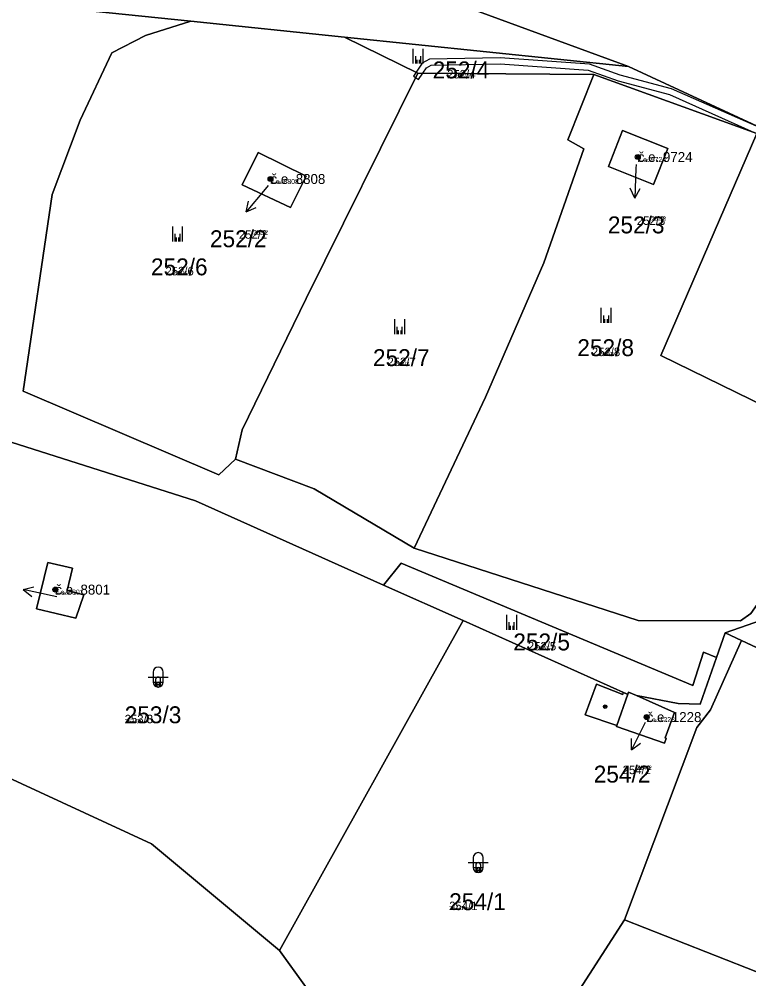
# Model space of a CAD drawing. Extents: x -759873 to -758487, y -975024 to -973516.
# Drawn here: x -758938.2 to -758864.9, y -974680.9 to -974584.4 of the extents above; entities that cross this region are included whole.
import ezdxf

# ---------------------------------------------------------------- set-up
doc = ezdxf.new("R2010")
doc.units = 0
for name, color, linetype in [('KAT_02_hranice parcel', 7, 'Continuous'), ('KAT_03_1000_st čísla parcelní', 7, 'Continuous'), ('KAT_03_1000_čísla parcelní', 7, 'Continuous'), ('KAT_03_1000_čísla popisná', 7, 'Continuous'), ('KAT_03_250_st čísla parcelní', 7, 'Continuous'), ('KAT_03_250_čísla parcelní', 7, 'Continuous'), ('KAT_03_250_čísla popisná', 7, 'Continuous'), ('KAT_03_500_st čísla parcelní', 7, 'Continuous'), ('KAT_03_500_čísla parcelní', 7, 'Continuous'), ('KAT_03_500_čísla popisná', 7, 'Continuous'), ('KAT_04_vnitřní kresba', 7, 'Continuous'), ('KAT_05_1000_značky kultur', 7, 'Continuous'), ('KAT_05_250_značky kultur', 7, 'Continuous'), ('KAT_05_500_značky kultur', 7, 'Continuous'), ('KAT_07_1000_značky budov', 7, 'Continuous'), ('KAT_07_250_značky budov', 7, 'Continuous'), ('KAT_07_500_značky budov', 7, 'Continuous'), ('KAT_10_věcná břemena', 7, 'Continuous'), ('KAT_12_pomocná šipka', 7, 'Continuous'), ('KAT_14_plocha_budovy', 7, 'Continuous'), ('KAT_14_plocha_pozemek', 7, 'Continuous')]:
    doc.layers.add(name, color=color, linetype=linetype)

msp = doc.modelspace()

# ---------------------------------------------------------------- linework, layer by layer
at = {"layer": 'KAT_02_hranice parcel'}
for p, q in [((-758920.93, -974584.62), (-758905.47, -974586.23)), ((-758905.47, -974586.23), (-758876.96, -974589.19)), ((-758905.47, -974586.23), (-758898.12, -974589.84)), ((-758898.12, -974589.84), (-758880.42, -974589.99)), ((-758880.42, -974589.99), (-758864.06, -974595.92)), ((-758893.55, -974644.86), (-758901.56, -974641.28)), ((-758912, -974678.02), (-758893.55, -974644.86)), ((-758877.14, -974652.2), (-758893.55, -974644.86)), ((-758868.1, -974648.55), (-758867.23, -974646.1)), ((-758865.59, -974646.87), (-758867.23, -974646.1)), ((-758830.87, -974663.12), (-758865.59, -974646.87)), ((-758892.74, -974704.7), (-758912, -974678.02))]:
    msp.add_line(p, q, dxfattribs=at)
for points in [[(-758909.19, -974563.8), (-758909.74, -974577.13), (-758876.96, -974589.19)], [(-758955.3, -974621.73), (-758944.2, -974593.65), (-758945.57, -974582.06), (-758920.93, -974584.62)], [(-758916.42, -974628.64), (-758918.11, -974630.21), (-758937.75, -974621.79), (-758934.83, -974602.03), (-758932.04, -974594.56), (-758928.85, -974587.8), (-758925.48, -974586.06), (-758920.93, -974584.62)], [(-758916.42, -974628.64), (-758915.75, -974625.68), (-758909.34, -974612.49), (-758898.12, -974589.84)], [(-758898.47, -974637.56), (-758891.31, -974622.41), (-758885.45, -974608.9), (-758881.45, -974597.46), (-758883.04, -974596.56), (-758880.42, -974589.99)], [(-758876.96, -974589.19), (-758848.43, -974602.4), (-758848.79, -974603.63)], [(-758873, -974597.42), (-758877.55, -974595.6), (-758878.95, -974599.23), (-758874.43, -974601.04), (-758873, -974597.42)], [(-758855.85, -974627.6), (-758861.57, -974624.14), (-758873.69, -974618.23), (-758864.06, -974595.92)], [(-758909.34, -974600.2), (-758914.17, -974597.83), (-758915.76, -974601.08), (-758910.91, -974603.34), (-758909.34, -974600.2)], [(-758955.3, -974621.73), (-758920.45, -974632.82), (-758901.56, -974641.28)], [(-758898.47, -974637.56), (-758908.53, -974631.63), (-758916.42, -974628.64)], [(-758857.61, -974633.6), (-758860.88, -974638), (-758862.68, -974641.33), (-758864.67, -974644.15), (-758865.71, -974644.88), (-758875.98, -974644.85), (-758898.47, -974637.56)], [(-758867.23, -974646.1), (-758860.6, -974643.76), (-758857.61, -974633.6)], [(-758932.8, -974639.6), (-758935.28, -974639.01), (-758936.41, -974643.67), (-758932.46, -974644.62), (-758931.67, -974642.25), (-758933.33, -974641.84), (-758932.8, -974639.6)], [(-758901.56, -974641.28), (-758899.78, -974639.1), (-758870.5, -974651.39), (-758869.41, -974648.04), (-758868.1, -974648.55)], [(-758877.35, -974674.93), (-758870.1, -974655.59), (-758868.73, -974653.83), (-758865.59, -974646.87)], [(-758868.1, -974648.55), (-758869.77, -974653.24), (-758871.96, -974653.19), (-758876.14, -974652.39)], [(-758876.14, -974652.39), (-758872.34, -974654.1), (-758873.26, -974656.65), (-758873.16, -974656.69), (-758873.33, -974657.16), (-758878.17, -974655.5), (-758878.14, -974655.39), (-758881.32, -974654.34), (-758880.17, -974651.24), (-758877.52, -974652.27), (-758877.48, -974652.09), (-758877.14, -974652.2)], [(-758876.14, -974652.39), (-758876.95, -974652.03), (-758877.01, -974652.25), (-758877.14, -974652.2)], [(-758912, -974678.02), (-758924.86, -974667.29), (-758949.14, -974656.07)], [(-758830.87, -974663.12), (-758834.94, -974670.75), (-758841.44, -974684.62), (-758853.59, -974681.81), (-758863.06, -974680.54), (-758877.35, -974674.93)], [(-758892.74, -974704.7), (-758892.08, -974697.79), (-758877.35, -974674.93)]]:
    msp.add_lwpolyline(points, dxfattribs=at)
at = {"layer": 'KAT_03_1000_čísla popisná'}
for centre in [(-758876.02, -974598.27), (-758912.91, -974600.48), (-758934.53, -974641.74), (-758875.13, -974654.55)]:
    msp.add_circle(centre, 0.25, dxfattribs=at)
at = {"layer": 'KAT_03_250_čísla popisná'}
for centre in [(-758876.02, -974598.27), (-758912.91, -974600.48), (-758934.53, -974641.74), (-758875.13, -974654.55)]:
    msp.add_circle(centre, 0.0625, dxfattribs=at)
at = {"layer": 'KAT_03_500_čísla popisná'}
for centre in [(-758876.02, -974598.27), (-758912.91, -974600.48), (-758934.53, -974641.74), (-758875.13, -974654.55)]:
    msp.add_circle(centre, 0.125, dxfattribs=at)
at = {"layer": 'KAT_04_vnitřní kresba'}
msp.add_line((-758878.14, -974655.39), (-758877.01, -974652.25), dxfattribs=at)
at = {"layer": 'KAT_05_1000_značky kultur'}
for p, q in [((-758898.581, -974588.89), (-758898.581, -974587.39)), ((-758897.58, -974588.89), (-758897.58, -974587.39)), ((-758922.741, -974606.75), (-758922.741, -974605.25)), ((-758921.74, -974606.75), (-758921.74, -974605.25)), ((-758879.701, -974614.94), (-758879.701, -974613.44)), ((-758878.7, -974614.94), (-758878.7, -974613.44)), ((-758900.431, -974616.08), (-758900.431, -974614.58)), ((-758899.43, -974616.08), (-758899.43, -974614.58)), ((-758889.181, -974645.77), (-758889.181, -974644.27)), ((-758888.18, -974645.77), (-758888.18, -974644.27)), ((-758925.201, -974650.531), (-758923.199, -974650.531)), ((-758924.701, -974650.031), (-758924.701, -974651.032)), ((-758923.699, -974651.032), (-758923.699, -974650.031)), ((-758892.551, -974668.671), (-758892.551, -974669.672)), ((-758891.549, -974669.672), (-758891.549, -974668.671)), ((-758893.051, -974669.171), (-758891.049, -974669.171))]:
    msp.add_line(p, q, dxfattribs=at)
for centre, start, end in [((-758924.2, -974650.031), 0, 180), ((-758924.2, -974651.031), 180, 359.98789), ((-758892.05, -974668.671), 0, 180), ((-758892.05, -974669.671), 180, 359.98789)]:
    msp.add_arc(centre, 0.5, start, end, dxfattribs=at)
at = {"layer": 'KAT_05_250_značky kultur'}
for p, q in [((-758898.198, -974588.89), (-758898.198, -974588.515)), ((-758897.948, -974588.89), (-758897.948, -974588.515)), ((-758922.358, -974606.75), (-758922.358, -974606.375)), ((-758922.108, -974606.75), (-758922.108, -974606.375)), ((-758879.318, -974614.94), (-758879.318, -974614.565)), ((-758879.068, -974614.94), (-758879.068, -974614.565)), ((-758900.048, -974616.08), (-758900.048, -974615.705)), ((-758899.797, -974616.08), (-758899.797, -974615.705)), ((-758888.798, -974645.77), (-758888.798, -974645.395)), ((-758888.547, -974645.77), (-758888.547, -974645.395)), ((-758924.45, -974651.28), (-758923.95, -974651.28)), ((-758924.325, -974651.155), (-758924.325, -974651.405)), ((-758924.075, -974651.405), (-758924.075, -974651.155)), ((-758892.3, -974669.92), (-758891.8, -974669.92)), ((-758892.175, -974669.795), (-758892.175, -974670.046)), ((-758891.925, -974670.046), (-758891.925, -974669.795))]:
    msp.add_line(p, q, dxfattribs=at)
for centre, start, end in [((-758924.2, -974651.155), 0, 180), ((-758924.2, -974651.405), 180, 359.98789), ((-758892.05, -974669.795), 0, 180), ((-758892.05, -974670.045), 180, 359.98789)]:
    msp.add_arc(centre, 0.125, start, end, dxfattribs=at)
at = {"layer": 'KAT_05_500_značky kultur'}
for p, q in [((-758898.326, -974588.89), (-758898.326, -974588.14)), ((-758897.825, -974588.89), (-758897.825, -974588.14)), ((-758922.486, -974606.75), (-758922.486, -974606)), ((-758921.985, -974606.75), (-758921.985, -974606)), ((-758879.446, -974614.94), (-758879.446, -974614.19)), ((-758878.945, -974614.94), (-758878.945, -974614.19)), ((-758900.176, -974616.08), (-758900.176, -974615.33)), ((-758899.675, -974616.08), (-758899.675, -974615.33)), ((-758888.926, -974645.77), (-758888.926, -974645.02)), ((-758888.425, -974645.77), (-758888.425, -974645.02)), ((-758924.701, -974651.03), (-758923.699, -974651.03)), ((-758924.451, -974650.78), (-758924.451, -974651.281)), ((-758923.949, -974651.281), (-758923.949, -974650.78)), ((-758892.551, -974669.671), (-758891.549, -974669.671)), ((-758892.301, -974669.421), (-758892.301, -974669.921)), ((-758891.799, -974669.921), (-758891.799, -974669.421))]:
    msp.add_line(p, q, dxfattribs=at)
for centre, start, end in [((-758924.2, -974650.78), 0, 180), ((-758924.2, -974651.28), 180, 359.98789), ((-758892.05, -974669.42), 0, 180), ((-758892.05, -974669.92), 180, 359.98789)]:
    msp.add_arc(centre, 0.25, start, end, dxfattribs=at)
at = {"layer": 'KAT_07_1000_značky budov'}
for centre in [(-758876.027, -974598.269), (-758912.917, -974600.479), (-758934.537, -974641.739), (-758879.297, -974653.499), (-758875.137, -974654.549)]:
    msp.add_circle(centre, 0.175, dxfattribs=at)
at = {"layer": 'KAT_07_250_značky budov'}
for centre in [(-758876.022, -974598.27), (-758912.912, -974600.48), (-758934.532, -974641.74), (-758879.292, -974653.5), (-758875.132, -974654.55)]:
    msp.add_circle(centre, 0.0437, dxfattribs=at)
at = {"layer": 'KAT_07_500_značky budov'}
for centre in [(-758876.023, -974598.27), (-758912.913, -974600.48), (-758934.533, -974641.74), (-758879.293, -974653.5), (-758875.133, -974654.55)]:
    msp.add_circle(centre, 0.0875, dxfattribs=at)
at = {"layer": 'KAT_10_věcná břemena'}
msp.add_lwpolyline([(-758863.78, -974595.29), (-758872.63, -974591.42), (-758877.8, -974590.03), (-758880.87, -974588.95), (-758889.84, -974588.31), (-758896.94, -974588.45), (-758897.67, -974588.85), (-758898.29, -974589.76), (-758898.56, -974590.15), (-758898.34, -974590.29), (-758898.06, -974590.49), (-758897.62, -974589.84), (-758897.25, -974589.31), (-758896.78, -974589.05), (-758889.86, -974588.91), (-758880.99, -974589.55), (-758877.98, -974590.61), (-758872.83, -974591.98), (-758864.34, -974595.82)], dxfattribs=at)
at = {"layer": 'KAT_12_pomocná šipka'}
for p, q in [((-758876.21, -974599.41), (-758876.315, -974602.409)), ((-758876.2, -974599.03), (-758876.21, -974599.41)), ((-758913.44, -974601.49), (-758915.369, -974603.789)), ((-758913.14, -974601.13), (-758913.44, -974601.49)), ((-758876.315, -974602.409), (-758876.78, -974601.391)), ((-758876.315, -974602.409), (-758875.779, -974601.426)), ((-758915.369, -974603.789), (-758915.109, -974602.7)), ((-758915.369, -974603.789), (-758914.342, -974603.344)), ((-758937.765, -974641.746), (-758936.682, -974641.464)), ((-758934.83, -974642.37), (-758937.765, -974641.746)), ((-758937.765, -974641.746), (-758936.89, -974642.444)), ((-758934.37, -974642.47), (-758934.83, -974642.37)), ((-758875.3, -974655.16), (-758876.662, -974657.834)), ((-758875.27, -974655.1), (-758875.3, -974655.16)), ((-758876.662, -974657.834), (-758876.654, -974656.714)), ((-758876.662, -974657.834), (-758875.762, -974657.169))]:
    msp.add_line(p, q, dxfattribs=at)
at = {"layer": 'KAT_14_plocha_budovy'}
for points in [[(-758878.95, -974599.23), (-758874.43, -974601.04), (-758873, -974597.42), (-758877.55, -974595.6)], [(-758915.76, -974601.08), (-758910.91, -974603.34), (-758909.34, -974600.2), (-758914.17, -974597.83)], [(-758936.41, -974643.67), (-758932.46, -974644.62), (-758931.67, -974642.25), (-758933.33, -974641.84), (-758932.8, -974639.6), (-758935.28, -974639.01)], [(-758873.26, -974656.65), (-758872.34, -974654.1), (-758876.14, -974652.39), (-758876.95, -974652.03), (-758877.01, -974652.25), (-758878.14, -974655.39), (-758878.17, -974655.5), (-758873.33, -974657.16), (-758873.16, -974656.69)]]:
    msp.add_lwpolyline(points, close=True, dxfattribs=at)
at = {"layer": 'KAT_14_plocha_pozemek'}
for points in [[(-759016.55, -974568.17), (-758996.05, -974575.76), (-758974.89, -974553.65), (-758967.25, -974543.68), (-758953.35, -974536.7), (-758933.95, -974536.82), (-758924.53, -974539.9), (-758913.57, -974550.46), (-758909.19, -974563.8), (-758909.74, -974577.13), (-758876.96, -974589.19), (-758848.43, -974602.4), (-758848.79, -974603.63), (-758855.85, -974627.6), (-758857.61, -974633.6), (-758860.6, -974643.76), (-758867.23, -974646.1), (-758865.59, -974646.87), (-758830.87, -974663.12), (-758829.75, -974663.64), (-758800.69, -974679.14)], [(-758945.57, -974582.06), (-758920.93, -974584.62), (-758905.47, -974586.23), (-758876.96, -974589.19), (-758909.74, -974577.13), (-758909.19, -974563.8), (-758923.96, -974567.7), (-758943.27, -974566.59)], [(-758864.67, -974644.15), (-758865.71, -974644.88), (-758875.98, -974644.85), (-758898.47, -974637.56), (-758908.53, -974631.63), (-758916.42, -974628.64), (-758918.11, -974630.21), (-758937.75, -974621.79), (-758934.83, -974602.03), (-758932.04, -974594.56), (-758928.85, -974587.8), (-758925.48, -974586.06), (-758920.93, -974584.62), (-758945.57, -974582.06)], [(-758955.3, -974621.73), (-758920.45, -974632.82), (-758901.56, -974641.28), (-758899.78, -974639.1), (-758870.5, -974651.39), (-758869.41, -974648.04), (-758868.1, -974648.55), (-758867.23, -974646.1), (-758860.6, -974643.76)]]:
    msp.add_lwpolyline(points, dxfattribs=at)
for points in [[(-758898.12, -974589.84), (-758905.47, -974586.23), (-758920.93, -974584.62), (-758925.48, -974586.06), (-758928.85, -974587.8), (-758932.04, -974594.56), (-758934.83, -974602.03), (-758937.75, -974621.79), (-758918.11, -974630.21), (-758916.42, -974628.64), (-758915.75, -974625.68), (-758909.34, -974612.49)], [(-758864.06, -974595.92), (-758852.74, -974601.3), (-758848.79, -974603.63), (-758848.43, -974602.4), (-758876.96, -974589.19), (-758905.47, -974586.23), (-758898.12, -974589.84), (-758880.42, -974589.99)], [(-758880.42, -974589.99), (-758898.12, -974589.84), (-758909.34, -974612.49), (-758915.75, -974625.68), (-758916.42, -974628.64), (-758908.53, -974631.63), (-758898.47, -974637.56), (-758891.31, -974622.41), (-758885.45, -974608.9), (-758881.45, -974597.46), (-758883.04, -974596.56)], [(-758855.85, -974627.6), (-758861.57, -974624.14), (-758873.69, -974618.23), (-758864.06, -974595.92), (-758880.42, -974589.99), (-758883.04, -974596.56), (-758881.45, -974597.46), (-758885.45, -974608.9), (-758891.31, -974622.41), (-758898.47, -974637.56), (-758875.98, -974644.85), (-758865.71, -974644.88), (-758864.67, -974644.15), (-758862.68, -974641.33), (-758860.88, -974638), (-758857.61, -974633.6)], [(-758873, -974597.42), (-758877.55, -974595.6), (-758878.95, -974599.23), (-758874.43, -974601.04)], [(-758873, -974597.42), (-758874.43, -974601.04), (-758878.95, -974599.23), (-758877.55, -974595.6)], [(-758855.85, -974627.6), (-758848.79, -974603.63), (-758852.74, -974601.3), (-758864.06, -974595.92), (-758873.69, -974618.23), (-758861.57, -974624.14)], [(-758909.34, -974600.2), (-758914.17, -974597.83), (-758915.76, -974601.08), (-758910.91, -974603.34)], [(-758909.34, -974600.2), (-758910.91, -974603.34), (-758915.76, -974601.08), (-758914.17, -974597.83)], [(-758893.55, -974644.86), (-758901.56, -974641.28), (-758920.45, -974632.82), (-758955.3, -974621.73), (-758954.3, -974627.31), (-758949.14, -974656.07), (-758924.86, -974667.29), (-758912, -974678.02)], [(-758932.8, -974639.6), (-758935.28, -974639.01), (-758936.41, -974643.67), (-758932.46, -974644.62), (-758931.67, -974642.25), (-758933.33, -974641.84)], [(-758932.8, -974639.6), (-758933.33, -974641.84), (-758931.67, -974642.25), (-758932.46, -974644.62), (-758936.41, -974643.67), (-758935.28, -974639.01)], [(-758868.1, -974648.55), (-758869.41, -974648.04), (-758870.5, -974651.39), (-758899.78, -974639.1), (-758901.56, -974641.28), (-758893.55, -974644.86), (-758877.14, -974652.2), (-758877.01, -974652.25), (-758876.95, -974652.03), (-758876.14, -974652.39), (-758871.96, -974653.19), (-758869.77, -974653.24)], [(-758868.1, -974648.55), (-758869.77, -974653.24), (-758871.96, -974653.19), (-758876.14, -974652.39), (-758872.34, -974654.1), (-758873.26, -974656.65), (-758873.16, -974656.69), (-758873.33, -974657.16), (-758878.17, -974655.5), (-758878.14, -974655.39), (-758881.32, -974654.34), (-758880.17, -974651.24), (-758877.52, -974652.27), (-758877.48, -974652.09), (-758877.14, -974652.2), (-758893.55, -974644.86), (-758912, -974678.02), (-758892.74, -974704.7), (-758892.08, -974697.79), (-758877.35, -974674.93), (-758870.1, -974655.59), (-758868.73, -974653.83), (-758865.59, -974646.87), (-758867.23, -974646.1)], [(-758830.87, -974663.12), (-758865.59, -974646.87), (-758868.73, -974653.83), (-758870.1, -974655.59), (-758877.35, -974674.93), (-758863.06, -974680.54), (-758853.59, -974681.81), (-758841.44, -974684.62), (-758834.94, -974670.75)], [(-758876.14, -974652.39), (-758876.95, -974652.03), (-758877.01, -974652.25), (-758877.14, -974652.2), (-758877.48, -974652.09), (-758877.52, -974652.27), (-758880.17, -974651.24), (-758881.32, -974654.34), (-758878.14, -974655.39), (-758878.17, -974655.5), (-758873.33, -974657.16), (-758873.16, -974656.69), (-758873.26, -974656.65), (-758872.34, -974654.1)], [(-758940.86, -974702.19), (-758933.79, -974733.82), (-758918.15, -974740.92), (-758892.74, -974704.7), (-758912, -974678.02), (-758924.86, -974667.29), (-758949.14, -974656.07)], [(-758830.87, -974663.12), (-758834.94, -974670.75), (-758841.44, -974684.62), (-758853.59, -974681.81), (-758863.06, -974680.54), (-758877.35, -974674.93), (-758892.08, -974697.79), (-758892.74, -974704.7), (-758858.23, -974722.43), (-758855, -974716.35), (-758846.61, -974699.26), (-758838.64, -974683.01), (-758833.34, -974672.35), (-758802.92, -974684.85), (-758800.69, -974679.14), (-758829.75, -974663.64)]]:
    msp.add_lwpolyline(points, close=True, dxfattribs=at)

# ---------------------------------------------------------------- texts
at = {"layer": 'KAT_03_1000_st čísla parcelní'}
for s, p in [('252/3', (-758879.026, -974605.943)), ('252/2', (-758918.996, -974607.333)), ('254/2', (-758880.446, -974661.133))]:
    msp.add_text(s, height=1.7, dxfattribs=at).set_placement(p)
at = {"layer": 'KAT_03_1000_čísla parcelní'}
for s, p in [('252/4', (-758896.623, -974590.37)), ('252/6', (-758924.923, -974610.16)), ('252/8', (-758882.093, -974618.28)), ('252/7', (-758902.623, -974619.28)), ('252/5', (-758888.523, -974647.85)), ('253/3', (-758927.56, -974655.169)), ('254/1', (-758894.97, -974673.95))]:
    msp.add_text(s, height=1.7, dxfattribs=at).set_placement(p)
at = {"layer": 'KAT_03_1000_čísla popisná'}
for s, p in [('č.e. 9724', (-758876.02, -974598.77)), ('č.e. 8808', (-758912.91, -974600.98)), ('č.e. 8801', (-758934.53, -974642.24)), ('č.e. 1228', (-758875.13, -974655.05))]:
    msp.add_text(s, height=1, dxfattribs=at).set_placement(p)
at = {"layer": 'KAT_03_250_st čísla parcelní'}
for s, p in [('252/3', (-758874.651, -974604.668)), ('252/2', (-758914.635, -974606.058)), ('254/2', (-758876.085, -974659.858))]:
    msp.add_text(s, height=0.425, dxfattribs=at).set_placement(p)
at = {"layer": 'KAT_03_250_čísla parcelní'}
for s, p in [('252/4', (-758894.438, -974590.37)), ('252/6', (-758922.735, -974610.16)), ('252/8', (-758879.905, -974618.28)), ('252/7', (-758900.435, -974619.28)), ('252/5', (-758886.331, -974647.85)), ('253/3', (-758927.56, -974655.169)), ('254/1', (-758894.97, -974673.95))]:
    msp.add_text(s, height=0.425, dxfattribs=at).set_placement(p)
at = {"layer": 'KAT_03_250_čísla popisná'}
for s, p in [('č.e. 9724', (-758876.02, -974598.77)), ('č.e. 8808', (-758912.91, -974600.98)), ('č.e. 8801', (-758934.53, -974642.24)), ('č.e. 1228', (-758875.13, -974655.05))]:
    msp.add_text(s, height=0.25, dxfattribs=at).set_placement(p)
at = {"layer": 'KAT_03_500_st čísla parcelní'}
for s, p in [('252/3', (-758876.109, -974605.093)), ('252/2', (-758916.088, -974606.483)), ('254/2', (-758877.538, -974660.283))]:
    msp.add_text(s, height=0.85, dxfattribs=at).set_placement(p)
at = {"layer": 'KAT_03_500_čísla parcelní'}
for s, p in [('252/4', (-758895.167, -974590.37)), ('252/6', (-758923.465, -974610.16)), ('252/8', (-758880.634, -974618.28)), ('252/7', (-758901.165, -974619.28)), ('252/5', (-758887.061, -974647.85)), ('253/3', (-758927.56, -974655.169)), ('254/1', (-758894.97, -974673.95))]:
    msp.add_text(s, height=0.85, dxfattribs=at).set_placement(p)
at = {"layer": 'KAT_03_500_čísla popisná'}
for s, p in [('č.e. 9724', (-758876.02, -974598.77)), ('č.e. 8808', (-758912.91, -974600.98)), ('č.e. 8801', (-758934.53, -974642.24)), ('č.e. 1228', (-758875.13, -974655.05))]:
    msp.add_text(s, height=0.5, dxfattribs=at).set_placement(p)

doc.saveas('drawing.dxf')
